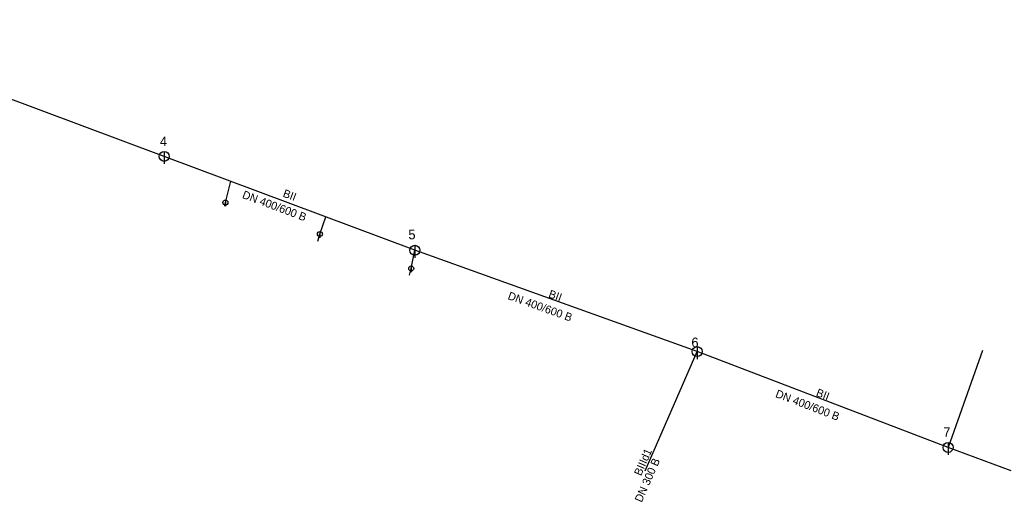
# Model space of a CAD drawing. Extents: x -464617 to -464210, y -1094294 to -1093929.
# Drawn here: x -464408.8 to -464210.1, y -1094294 to -1094197.3 of the extents above; entities that cross this region are included whole.
import ezdxf

# ---------------------------------------------------------------- set-up
doc = ezdxf.new("R2010")
doc.units = 0
for name, color, linetype in [('_pripojka_kanal_jednotna_prevzato_z_dokumentace_', 7, 'Continuous'), ('_pripojka_kanal_jednotna_priblizne_', 7, 'Continuous'), ('_stoka_jednotna_smvak_prevzato_z_dokumentace_', 7, 'Continuous'), ('Default', 7, 'Continuous'), ('MoLevel 119', 7, 'Continuous'), ('MoLevel 120', 7, 'Continuous'), ('MoLevel 57', 7, 'Continuous'), ('MoLevel 68', 7, 'Continuous'), ('MoLevel 69', 7, 'Continuous')]:
    doc.layers.add(name, color=color, linetype=linetype)

# ---------------------------------------------------------------- blocks, each defined once
blk = doc.blocks.new('_sachta_kanal_prip_')
at = {"layer": 'Default'}
blk.add_line((0, 0.00005), (0, -0.000075), dxfattribs=at)
blk.add_circle((0, 0), 0.00005, dxfattribs=at)
blk = doc.blocks.new('_sachta_kanal_prevzato_z_dokumentace_')
at = {"layer": 'Default'}
blk.add_line((0, 0.00005), (0, -0.000075), dxfattribs=at)
blk.add_circle((0, 0), 0.00005, dxfattribs=at)

msp = doc.modelspace()

# ---------------------------------------------------------------- linework, layer by layer
at = {"layer": '_pripojka_kanal_jednotna_prevzato_z_dokumentace_'}
msp.add_line((-464215.83, -1094263.57), (-464222.73, -1094282.99), dxfattribs=at)
at = {"layer": '_pripojka_kanal_jednotna_priblizne_'}
for p, q in [((-464367.61, -1094233.91), (-464366.53, -1094229.65)), ((-464367.71, -1094234.66), (-464367.61, -1094233.91)), ((-464348.66, -1094240.21), (-464347.51, -1094236.77)), ((-464349.05, -1094241.63), (-464348.66, -1094240.21)), ((-464330.36, -1094247.12), (-464329.64, -1094243.47)), ((-464330.68, -1094248.48), (-464330.36, -1094247.12))]:
    msp.add_line(p, q, dxfattribs=at)
at = {"layer": '_stoka_jednotna_smvak_prevzato_z_dokumentace_'}
for p, q in [((-464379.88, -1094224.65), (-464453.2, -1094197.28)), ((-464329.64, -1094243.47), (-464379.88, -1094224.65)), ((-464273.04, -1094263.78), (-464329.64, -1094243.47)), ((-464283.47, -1094287.71), (-464273.04, -1094263.78)), ((-464222.73, -1094282.99), (-464273.04, -1094263.78)), ((-464210.09, -1094287.71), (-464222.73, -1094282.99))]:
    msp.add_line(p, q, dxfattribs=at)

# ---------------------------------------------------------------- block references
at = {"layer": 'MoLevel 119', "xscale": 20000, "yscale": 20000}
for p in [(-464379.88, -1094224.65), (-464329.64, -1094243.47), (-464273.04, -1094263.78), (-464222.73, -1094282.99)]:
    msp.add_blockref('_sachta_kanal_prevzato_z_dokumentace_', p, dxfattribs=at)
at = {"layer": 'MoLevel 57', "xscale": 10000, "yscale": 10000}
for p in [(-464367.61, -1094233.91), (-464348.66, -1094240.21), (-464330.36, -1094247.12)]:
    msp.add_blockref('_sachta_kanal_prip_', p, dxfattribs=at)

# ---------------------------------------------------------------- texts
at = {"layer": 'MoLevel 120'}
for s, p in [('4', (-464380.75, -1094222.6)), ('5', (-464330.93, -1094241.27)), ('6', (-464274.19, -1094262.9)), ('7', (-464223.7, -1094280.88))]:
    msp.add_text(s, height=1.93, dxfattribs=at).set_placement(p)
at = {"layer": 'MoLevel 68'}
for s, height, rotation, p in [('DN 400/600 B', 1.6049, 339.464, (-464364.37, -1094232.95)), ('DN 400/600 B', 1.6049, 340.2603, (-464311.13, -1094253.23)), ('DN 400/600 B', 1.6049, 339.1015, (-464257.48, -1094272.85)), ('DN 300 B', 1.605, 66.4529, (-464284.16, -1094294.12))]:
    msp.add_text(s, height=height, rotation=rotation, dxfattribs=at).set_placement(p)
at = {"layer": 'MoLevel 69'}
for s, rotation, p in [('BII', 339.464, (-464356.22, -1094232.69)), ('BII', 340.2603, (-464302.97, -1094252.86)), ('BII', 339.1015, (-464249.34, -1094272.64)), ('BIIId1', 66.4529, (-464284.29, -1094288.8))]:
    msp.add_text(s, height=1.605, rotation=rotation, dxfattribs=at).set_placement(p)

doc.saveas('drawing.dxf')
